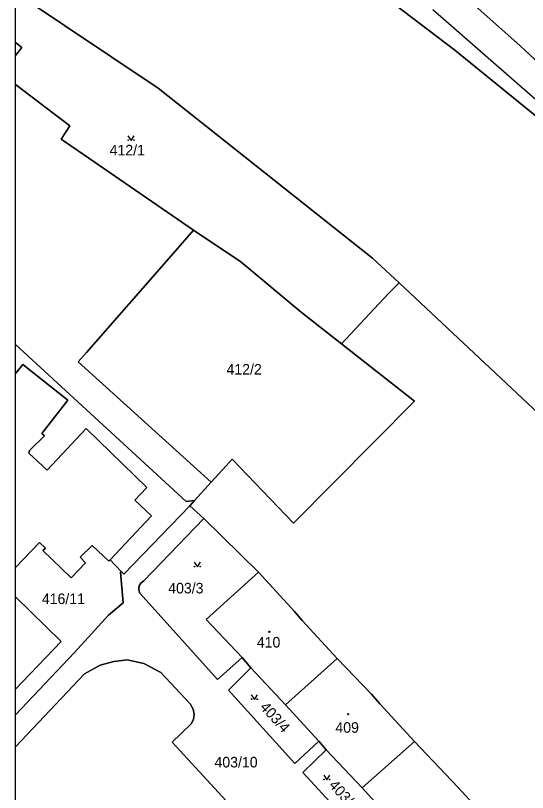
# Model space of a CAD drawing. Extents: x -598934 to -598196, y -1162208 to -1161502.
# Drawn here: x -598932 to -598849.5, y -1161868.2 to -1161742.9 of the extents above; entities that cross this region are included whole.
import ezdxf

# ---------------------------------------------------------------- set-up
doc = ezdxf.new("R2010")
doc.units = 0
for name, color, linetype in [('KN_CAR_KR', 7, 'Continuous'), ('KN_KULTURY', 7, 'Continuous'), ('KN_PARC_CIS_POZ', 7, 'Continuous'), ('KN_PARC_CIS_STAV', 7, 'Continuous'), ('KN_PARC_PLOCHA', 7, 'Continuous'), ('parcely_l', 7, 'Continuous')]:
    doc.layers.add(name, color=color, linetype=linetype)

msp = doc.modelspace()

# ---------------------------------------------------------------- linework, layer by layer
at = {"layer": 'KN_CAR_KR'}
for points in [[(-598861.34, -1161738.27), (-598850.63, -1161747.82)], [(-598864.7, -1161741.93), (-598839.67, -1161763.81)], [(-598850.63, -1161747.82), (-598820.04, -1161776.24)]]:
    msp.add_lwpolyline(points, dxfattribs=at)
at = {"layer": 'KN_KULTURY'}
for points in [[(-598913.89, -1161762.3), (-598913.39, -1161763.05), (-598912.89, -1161762.3)], [(-598903.18, -1161831.06), (-598902.68, -1161831.81), (-598902.18, -1161831.06)], [(-598894, -1161852.42), (-598893.5, -1161853.17), (-598893, -1161852.42)], [(-598882.3, -1161865.38), (-598881.8, -1161866.13), (-598881.3, -1161865.38)]]:
    msp.add_lwpolyline(points, dxfattribs=at)
for centre, radius in [((-598913.84, -1161763), 0.05), ((-598912.94, -1161763), 0.05), ((-598903.13, -1161831.76), 0.05), ((-598902.23, -1161831.76), 0.05), ((-598891.08, -1161842.27), 0.09), ((-598891.08, -1161842.27), 0.0398), ((-598893.95, -1161853.12), 0.05), ((-598893.05, -1161853.12), 0.05), ((-598878.38, -1161855.54), 0.09), ((-598878.38, -1161855.54), 0.0398), ((-598882.25, -1161866.08), 0.05), ((-598881.35, -1161866.08), 0.05)]:
    msp.add_circle(centre, radius, dxfattribs=at)
at = {"layer": 'KN_PARC_PLOCHA'}
for points in [[(-598737.15, -1161925.8), (-598813.1, -1161843.8), (-598846.83, -1161807.87), (-598870.15, -1161785.99), (-598874.43, -1161782.02), (-598909.01, -1161754.64), (-598931.6, -1161739.49), (-598932.02, -1161739.21), (-598932.02, -1161697.6), (-598929.76, -1161698.95), (-598910.52, -1161712.03), (-598888.91, -1161727.38), (-598861.19, -1161748.52), (-598845.68, -1161761.08), (-598825.17, -1161781.28), (-598821.65, -1161784.92), (-598808.06, -1161799.42), (-598788.14, -1161822.37), (-598718.78, -1161901.85)], [(-598833.54, -1161739.94), (-598820.14, -1161752.25), (-598815.41, -1161756.66), (-598814.73, -1161756.78), (-598812.32, -1161761.04), (-598809.07, -1161765.33), (-598815.82, -1161772.05), (-598820.04, -1161776.24), (-598823.72, -1161779.88), (-598825.17, -1161781.28), (-598845.68, -1161761.08), (-598861.19, -1161748.52), (-598888.91, -1161727.38)], [(-598855.16, -1161873.33), (-598860.69, -1161867.32), (-598867.65, -1161859.97), (-598873.24, -1161853.88), (-598874.59, -1161852.34), (-598880.14, -1161846.58), (-598885.8, -1161840.43), (-598887.04, -1161838.98), (-598892.84, -1161832.67), (-598901.66, -1161824.01), (-598903.88, -1161821.95), (-598903.15, -1161821.12), (-598900.46, -1161818.16), (-598898.03, -1161815.49), (-598897.09, -1161814.44), (-598887.21, -1161824.73), (-598867.65, -1161805.09), (-598879.44, -1161795.83), (-598873.42, -1161789.39), (-598871.79, -1161787.66), (-598870.15, -1161785.99), (-598846.83, -1161807.87), (-598813.1, -1161843.8), (-598737.15, -1161925.8)], [(-598893.09, -1161874.87), (-598906.75, -1161860.04), (-598903.7, -1161857.09), (-598903.33, -1161856.39), (-598903.22, -1161855.53), (-598903.36, -1161854.74), (-598903.83, -1161853.86), (-598908.56, -1161848.84), (-598911.35, -1161847.37), (-598914.02, -1161846.81), (-598916.16, -1161847.03), (-598918.35, -1161847.67), (-598920.92, -1161849.06), (-598932.02, -1161860.81), (-598932.02, -1161855.63), (-598922.52, -1161845.61), (-598917.04, -1161839.56), (-598914.67, -1161837.58), (-598915.11, -1161832.65), (-598914.99, -1161832.52), (-598914.56, -1161832.98), (-598903.88, -1161821.95), (-598901.66, -1161824.01), (-598911.35, -1161834.04), (-598911.82, -1161834.44), (-598912.06, -1161834.88), (-598912.14, -1161835.35), (-598912.01, -1161835.98), (-598911.45, -1161836.64), (-598899.46, -1161849.97), (-598895.48, -1161846.4), (-598894.09, -1161848.07), (-598897.66, -1161851.67), (-598886.97, -1161863.49), (-598883.1, -1161859.9), (-598881.92, -1161861.3), (-598885.67, -1161864.96), (-598874.39, -1161877.22)], [(-598932.02, -1161880.68), (-598932.02, -1161860.81), (-598920.92, -1161849.06), (-598918.35, -1161847.67), (-598916.16, -1161847.03), (-598914.02, -1161846.81), (-598911.35, -1161847.37), (-598908.56, -1161848.84), (-598903.83, -1161853.86), (-598903.36, -1161854.74), (-598903.22, -1161855.53), (-598903.33, -1161856.39), (-598903.7, -1161857.09), (-598906.75, -1161860.04), (-598893.09, -1161874.87)]]:
    msp.add_lwpolyline(points, dxfattribs=at)
for points in [[(-598870.15, -1161785.99), (-598871.79, -1161787.66), (-598873.42, -1161789.39), (-598879.44, -1161795.83), (-598885.94, -1161790.72), (-598895.69, -1161782.65), (-598903.31, -1161777.5), (-598919.33, -1161766.5), (-598924.65, -1161762.85), (-598923.28, -1161760.72), (-598932.02, -1161754.06), (-598932.02, -1161749.37), (-598931.02, -1161748.07), (-598932.02, -1161747.26), (-598932.02, -1161739.21), (-598931.6, -1161739.49), (-598909.01, -1161754.64), (-598874.43, -1161782.02)], [(-598931.02, -1161748.07), (-598932.02, -1161749.37), (-598932.02, -1161747.26)], [(-598903.15, -1161821.12), (-598904.52, -1161821.28), (-598932.02, -1161795.96), (-598932.02, -1161754.06), (-598923.28, -1161760.72), (-598924.65, -1161762.85), (-598919.33, -1161766.5), (-598903.31, -1161777.5), (-598906.93, -1161781.64), (-598920.56, -1161797.22), (-598921.9, -1161798.76), (-598900.46, -1161818.16)], [(-598879.44, -1161795.83), (-598867.65, -1161805.09), (-598887.21, -1161824.73), (-598897.09, -1161814.44), (-598898.03, -1161815.49), (-598900.46, -1161818.16), (-598921.9, -1161798.76), (-598920.56, -1161797.22), (-598906.93, -1161781.64), (-598903.31, -1161777.5), (-598895.69, -1161782.65), (-598885.94, -1161790.72)], [(-598903.15, -1161821.12), (-598903.88, -1161821.95), (-598914.56, -1161832.98), (-598914.99, -1161832.52), (-598916.74, -1161830.67), (-598910.07, -1161823.58), (-598912.77, -1161821.04), (-598910.84, -1161818.99), (-598920.6, -1161809.51), (-598926.91, -1161816.23), (-598929.86, -1161813.45), (-598929.75, -1161813.04), (-598927.35, -1161810.65), (-598927.78, -1161810.31), (-598923.56, -1161804.94), (-598930.84, -1161799.18), (-598931.95, -1161800.59), (-598932.02, -1161800.54), (-598932.02, -1161795.96), (-598904.52, -1161821.28)], [(-598916.74, -1161830.67), (-598916.96, -1161830.9), (-598919.68, -1161828.36), (-598921.59, -1161830.22), (-598920.71, -1161831.16), (-598923.03, -1161833.58), (-598927.6, -1161829.17), (-598927.21, -1161828.78), (-598928.14, -1161827.88), (-598932.02, -1161831.91), (-598932.02, -1161800.54), (-598931.95, -1161800.59), (-598930.84, -1161799.18), (-598923.56, -1161804.94), (-598927.78, -1161810.31), (-598927.35, -1161810.65), (-598929.75, -1161813.04), (-598929.86, -1161813.45), (-598926.91, -1161816.23), (-598920.6, -1161809.51), (-598910.84, -1161818.99), (-598912.77, -1161821.04), (-598910.07, -1161823.58)], [(-598892.84, -1161832.67), (-598901.28, -1161840.28), (-598895.48, -1161846.4), (-598899.46, -1161849.97), (-598911.45, -1161836.64), (-598912.01, -1161835.98), (-598912.14, -1161835.35), (-598912.06, -1161834.88), (-598911.82, -1161834.44), (-598911.35, -1161834.04), (-598901.66, -1161824.01)], [(-598916.74, -1161830.67), (-598914.99, -1161832.52), (-598915.11, -1161832.65), (-598914.67, -1161837.58), (-598917.04, -1161839.56), (-598922.52, -1161845.61), (-598932.02, -1161855.63), (-598932.02, -1161851.52), (-598924.68, -1161843.82), (-598932.02, -1161836.64), (-598932.02, -1161831.91), (-598928.14, -1161827.88), (-598927.21, -1161828.78), (-598927.6, -1161829.17), (-598923.03, -1161833.58), (-598920.71, -1161831.16), (-598921.59, -1161830.22), (-598919.68, -1161828.36), (-598916.96, -1161830.9)], [(-598880.14, -1161846.58), (-598888.47, -1161854.05), (-598894.09, -1161848.07), (-598895.48, -1161846.4), (-598901.28, -1161840.28), (-598892.84, -1161832.67), (-598887.04, -1161838.98), (-598885.8, -1161840.43)], [(-598932.02, -1161851.52), (-598932.02, -1161836.64), (-598924.68, -1161843.82)], [(-598867.65, -1161859.97), (-598876.1, -1161867.42), (-598881.92, -1161861.3), (-598883.1, -1161859.9), (-598888.47, -1161854.05), (-598880.14, -1161846.58), (-598874.59, -1161852.34), (-598873.24, -1161853.88)], [(-598888.47, -1161854.05), (-598883.1, -1161859.9), (-598886.97, -1161863.49), (-598897.66, -1161851.67), (-598894.09, -1161848.07)], [(-598855.16, -1161873.33), (-598863.63, -1161881.04), (-598870.53, -1161873.59), (-598876.1, -1161867.42), (-598867.65, -1161859.97), (-598860.69, -1161867.32)], [(-598876.1, -1161867.42), (-598870.53, -1161873.59), (-598874.39, -1161877.22), (-598885.67, -1161864.96), (-598881.92, -1161861.3)]]:
    msp.add_lwpolyline(points, close=True, dxfattribs=at)
at = {"layer": 'parcely_l'}
for points in [[(-598932.02, -1161697.6), (-598929.76, -1161698.95), (-598910.52, -1161712.03), (-598888.91, -1161727.38), (-598861.19, -1161748.52), (-598845.68, -1161761.08), (-598825.17, -1161781.28)], [(-598870.15, -1161785.99), (-598874.43, -1161782.02), (-598909.01, -1161754.64), (-598931.6, -1161739.49), (-598932.02, -1161739.21)], [(-598932.02, -1161747.26), (-598932.02, -1161739.21)], [(-598931.02, -1161748.07), (-598932.02, -1161747.26)], [(-598932.02, -1161749.37), (-598932.02, -1161747.26)], [(-598932.02, -1161749.37), (-598931.02, -1161748.07)], [(-598932.02, -1161754.06), (-598932.02, -1161749.37)], [(-598903.31, -1161777.5), (-598919.33, -1161766.5), (-598924.65, -1161762.85), (-598923.28, -1161760.72), (-598932.02, -1161754.06)], [(-598932.02, -1161795.96), (-598932.02, -1161754.06)], [(-598900.46, -1161818.16), (-598921.9, -1161798.76), (-598920.56, -1161797.22), (-598906.93, -1161781.64), (-598903.31, -1161777.5)], [(-598903.31, -1161777.5), (-598895.69, -1161782.65), (-598885.94, -1161790.72), (-598879.44, -1161795.83)], [(-598879.44, -1161795.83), (-598873.42, -1161789.39), (-598871.79, -1161787.66), (-598870.15, -1161785.99)], [(-598737.15, -1161925.8), (-598813.1, -1161843.8), (-598846.83, -1161807.87), (-598870.15, -1161785.99)], [(-598903.15, -1161821.12), (-598904.52, -1161821.28), (-598932.02, -1161795.96)], [(-598932.02, -1161800.54), (-598932.02, -1161795.96)], [(-598879.44, -1161795.83), (-598867.65, -1161805.09), (-598887.21, -1161824.73), (-598897.09, -1161814.44), (-598898.03, -1161815.49), (-598900.46, -1161818.16)], [(-598932.02, -1161800.54), (-598931.95, -1161800.59), (-598930.84, -1161799.18), (-598923.56, -1161804.94), (-598927.78, -1161810.31), (-598927.35, -1161810.65), (-598929.75, -1161813.04), (-598929.86, -1161813.45), (-598926.91, -1161816.23), (-598920.6, -1161809.51), (-598910.84, -1161818.99), (-598912.77, -1161821.04), (-598910.07, -1161823.58), (-598916.74, -1161830.67)], [(-598932.02, -1161831.91), (-598932.02, -1161800.54)], [(-598903.15, -1161821.12), (-598900.46, -1161818.16)], [(-598903.88, -1161821.95), (-598903.15, -1161821.12)], [(-598914.99, -1161832.52), (-598914.56, -1161832.98), (-598903.88, -1161821.95)], [(-598903.88, -1161821.95), (-598901.66, -1161824.01)], [(-598895.48, -1161846.4), (-598899.46, -1161849.97), (-598911.45, -1161836.64), (-598912.01, -1161835.98), (-598912.14, -1161835.35), (-598912.06, -1161834.88), (-598911.82, -1161834.44), (-598911.35, -1161834.04), (-598901.66, -1161824.01)], [(-598901.66, -1161824.01), (-598892.84, -1161832.67)], [(-598932.02, -1161831.91), (-598928.14, -1161827.88), (-598927.21, -1161828.78), (-598927.6, -1161829.17), (-598923.03, -1161833.58), (-598920.71, -1161831.16), (-598921.59, -1161830.22), (-598919.68, -1161828.36), (-598916.96, -1161830.9), (-598916.74, -1161830.67)], [(-598916.74, -1161830.67), (-598914.99, -1161832.52)], [(-598932.02, -1161836.64), (-598932.02, -1161831.91)], [(-598932.02, -1161855.63), (-598922.52, -1161845.61), (-598917.04, -1161839.56), (-598914.67, -1161837.58), (-598915.11, -1161832.65), (-598914.99, -1161832.52)], [(-598892.84, -1161832.67), (-598901.28, -1161840.28), (-598895.48, -1161846.4)], [(-598892.84, -1161832.67), (-598887.04, -1161838.98), (-598885.8, -1161840.43), (-598880.14, -1161846.58)], [(-598932.02, -1161851.52), (-598932.02, -1161836.64)], [(-598932.02, -1161836.64), (-598924.68, -1161843.82), (-598932.02, -1161851.52)], [(-598895.48, -1161846.4), (-598894.09, -1161848.07)], [(-598932.02, -1161860.81), (-598920.92, -1161849.06), (-598918.35, -1161847.67), (-598916.16, -1161847.03), (-598914.02, -1161846.81), (-598911.35, -1161847.37), (-598908.56, -1161848.84), (-598903.83, -1161853.86), (-598903.36, -1161854.74), (-598903.22, -1161855.53), (-598903.33, -1161856.39), (-598903.7, -1161857.09), (-598906.75, -1161860.04), (-598893.09, -1161874.87)], [(-598880.14, -1161846.58), (-598888.47, -1161854.05)], [(-598867.65, -1161859.97), (-598873.24, -1161853.88), (-598874.59, -1161852.34), (-598880.14, -1161846.58)], [(-598883.1, -1161859.9), (-598886.97, -1161863.49), (-598897.66, -1161851.67), (-598894.09, -1161848.07)], [(-598894.09, -1161848.07), (-598888.47, -1161854.05)], [(-598932.02, -1161855.63), (-598932.02, -1161851.52)], [(-598888.47, -1161854.05), (-598883.1, -1161859.9)], [(-598932.02, -1161860.81), (-598932.02, -1161855.63)], [(-598883.1, -1161859.9), (-598881.92, -1161861.3)], [(-598876.1, -1161867.42), (-598867.65, -1161859.97)], [(-598867.65, -1161859.97), (-598860.69, -1161867.32), (-598855.16, -1161873.33)], [(-598932.02, -1161880.68), (-598932.02, -1161860.81)], [(-598881.92, -1161861.3), (-598885.67, -1161864.96), (-598874.39, -1161877.22), (-598870.53, -1161873.59)], [(-598881.92, -1161861.3), (-598876.1, -1161867.42)], [(-598870.53, -1161873.59), (-598876.1, -1161867.42)]]:
    msp.add_lwpolyline(points, dxfattribs=at)

# ---------------------------------------------------------------- texts
at = {"layer": 'KN_PARC_CIS_POZ'}
for s, p in [('412/1', (-598916.84, -1161765.47)), ('412/2', (-598897.99, -1161800.8)), ('403/3', (-598907.39, -1161836.08)), ('416/11', (-598927.77, -1161837.79)), ('403/10', (-598899.93, -1161864.13))]:
    msp.add_text(s, height=1.7, dxfattribs=at).set_placement(p)
for s, p in [('403/4', (-598892.7, -1161854.49)), ('403/5', (-598881.59, -1161867.08))]:
    msp.add_text(s, height=1.7, rotation=312.3013, dxfattribs=at).set_placement(p)
at = {"layer": 'KN_PARC_CIS_STAV'}
for s, p in [('410', (-598893.1, -1161844.8)), ('409', (-598880.43, -1161858.54))]:
    msp.add_text(s, height=1.7, dxfattribs=at).set_placement(p)

doc.saveas('drawing.dxf')
